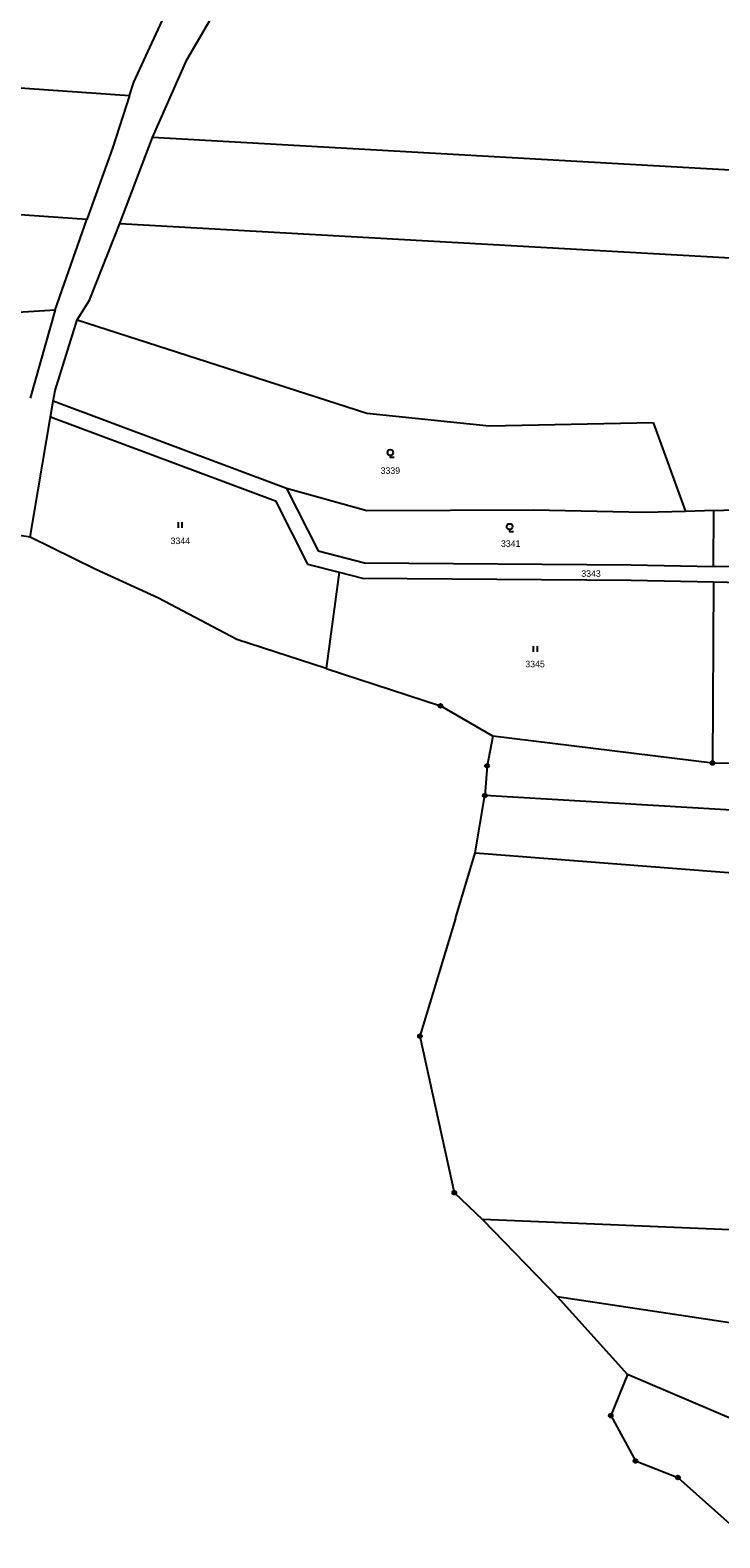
# Model space of a CAD drawing. Extents: x -618848 to -615803, y -1044450 to -1042254.
# Drawn here: x -617986.6 to -617807.4, y -1044320.6 to -1043928.7 of the extents above; entities that cross this region are included whole.
import ezdxf

# ---------------------------------------------------------------- set-up
doc = ezdxf.new("R2010")
doc.units = 0
doc.header["$LTSCALE"] = 0.68
for name, color, linetype, lineweight in [('1', 7, 'Continuous', 25), ('3', 7, 'Continuous', 25), ('8', 7, 'Continuous', 25)]:
    doc.layers.add(name, color=color, linetype=linetype, lineweight=lineweight)
doc.layers.add('2', color=7, linetype='Continuous')

msp = doc.modelspace()

# ---------------------------------------------------------------- linework, layer by layer
at = {"layer": '1'}
for p, q in [((-617959.62, -1043942.21), (-617950.21, -1043921.71)), ((-617945.87, -1043936.37), (-617936.21, -1043919.8)), ((-618090.57, -1043936.58), (-617960.75, -1043945.7)), ((-617954.79, -1043956.59), (-617945.87, -1043936.37)), ((-617960.75, -1043945.7), (-617959.62, -1043942.21)), ((-617960.75, -1043945.7), (-617965.15, -1043959.31)), ((-617963.26, -1043978.9), (-617954.79, -1043956.59)), ((-617810.87, -1043964.7), (-617954.79, -1043956.59)), ((-617965.15, -1043959.31), (-617971.8, -1043977.92)), ((-617666.94, -1043972.8), (-617810.87, -1043964.7)), ((-617971.8, -1043977.92), (-618093.61, -1043969.36)), ((-617980.1, -1044001.34), (-617971.8, -1043977.92)), ((-617971.13, -1043998.89), (-617963.26, -1043978.9)), ((-617963.26, -1043978.9), (-617816.94, -1043987.14)), ((-617816.94, -1043987.14), (-617670.61, -1043995.37)), ((-617974.35, -1044003.94), (-617971.13, -1043998.89)), ((-618083.54, -1044008.12), (-617980.1, -1044001.34)), ((-617980.1, -1044001.34), (-617986.59, -1044024.38)), ((-617980.1, -1044022.31), (-617974.35, -1044003.94)), ((-617974.35, -1044003.94), (-617899.12, -1044028.25)), ((-617980.58, -1044025.14), (-617980.1, -1044022.31)), ((-617981.26, -1044029.16), (-617980.58, -1044025.14)), ((-617919.95, -1044047.83), (-617980.58, -1044025.14)), ((-617986.53, -1044060.45), (-617981.26, -1044029.16)), ((-617981.26, -1044029.16), (-617922.82, -1044051.03)), ((-617899.12, -1044028.25), (-617867.32, -1044031.57)), ((-617867.32, -1044031.57), (-617824.69, -1044030.71)), ((-617824.69, -1044030.71), (-617816.28, -1044053.77)), ((-617922.82, -1044051.03), (-617914.5, -1044067.46)), ((-617919.95, -1044047.83), (-617911.75, -1044064.04)), ((-617899.09, -1044053.6), (-617919.95, -1044047.83)), ((-617855.68, -1044053.44), (-617899.09, -1044053.6)), ((-617826.98, -1044054.09), (-617855.68, -1044053.44)), ((-617816.28, -1044053.77), (-617826.98, -1044054.09)), ((-617808.93, -1044053.54), (-617816.28, -1044053.77)), ((-617809.02, -1044068.1), (-617808.93, -1044053.54)), ((-617808.93, -1044053.54), (-617759.25, -1044052.05)), ((-617986.53, -1044060.45), (-617991.04, -1044059.78)), ((-617969.64, -1044068.77), (-617986.53, -1044060.45)), ((-617911.75, -1044064.04), (-617899.66, -1044067.16)), ((-617953.23, -1044076.38), (-617969.64, -1044068.77)), ((-617914.5, -1044067.46), (-617906.24, -1044069.6)), ((-617906.24, -1044069.6), (-617909.69, -1044094.66)), ((-617906.24, -1044069.6), (-617900.19, -1044071.16)), ((-617899.66, -1044067.16), (-617830.39, -1044067.65)), ((-617830.39, -1044067.65), (-617809.02, -1044068.1)), ((-617788.2, -1044068.54), (-617809.02, -1044068.1)), ((-617900.19, -1044071.16), (-617830.44, -1044071.65)), ((-617830.44, -1044071.65), (-617809.04, -1044072.1)), ((-617809.04, -1044072.1), (-617809.32, -1044119.2)), ((-617809.04, -1044072.1), (-617787.18, -1044072.56)), ((-617932.9, -1044087.11), (-617953.23, -1044076.38)), ((-617909.69, -1044094.66), (-617932.9, -1044087.11)), ((-617909.69, -1044094.66), (-617879.95, -1044104.33)), ((-617866.32, -1044112.2), (-617879.95, -1044104.33)), ((-617866.32, -1044112.2), (-617867.85, -1044119.94)), ((-617867.85, -1044119.94), (-617868.44, -1044127.67)), ((-617870.92, -1044142.59), (-617868.44, -1044127.67)), ((-617790.18, -1044132.28), (-617868.44, -1044127.67)), ((-617876.05, -1044159.64), (-617870.92, -1044142.59)), ((-617870.92, -1044142.59), (-617790.88, -1044148.81)), ((-617876.05, -1044159.64), (-617885.29, -1044190.21)), ((-617885.29, -1044190.21), (-617876.38, -1044230.9)), ((-617876.38, -1044230.9), (-617869.01, -1044237.88)), ((-617869.01, -1044237.88), (-617849.67, -1044257.87)), ((-617784.3, -1044241.37), (-617869.01, -1044237.88)), ((-617849.67, -1044257.87), (-617831.39, -1044278.13)), ((-617849.67, -1044257.87), (-617787.93, -1044267.22)), ((-617831.39, -1044278.13), (-617835.71, -1044288.86)), ((-617782.08, -1044299.3), (-617831.39, -1044278.13)), ((-617835.71, -1044288.86), (-617829.3, -1044300.65)), ((-617829.3, -1044300.65), (-617818.27, -1044304.96))]:
    msp.add_line(p, q, dxfattribs=at)
for points in [[(-617714.6, -1044119.56), (-617809.32, -1044119.2), (-617866.32, -1044112.2)], [(-617818.27, -1044304.96), (-617803.97, -1044317.65), (-617795.59, -1044320.64)]]:
    msp.add_lwpolyline(points, dxfattribs=at)
at = {"layer": '3'}
for p, q in [((-617948.061, -1044058.05), (-617948.061, -1044056.55)), ((-617947.06, -1044058.05), (-617947.06, -1044056.55)), ((-617855.781, -1044090.29), (-617855.781, -1044088.79)), ((-617854.78, -1044090.29), (-617854.78, -1044088.79))]:
    msp.add_line(p, q, dxfattribs=at)
for points in [[(-617892.99, -1044039.212), (-617892.99, -1044039.71), (-617891.989, -1044039.71)], [(-617861.99, -1044058.482), (-617861.99, -1044058.98), (-617860.989, -1044058.98)]]:
    msp.add_lwpolyline(points, dxfattribs=at)
for centre in [(-617892.9893, -1044038.4609), (-617861.9893, -1044057.7309)]:
    msp.add_circle(centre, 0.75, dxfattribs=at)
at = {"layer": '8'}
for centre, radius in [((-617879.95, -1044104.3299), 0.5), ((-617879.95, -1044104.3299), 0.0303), ((-617867.85, -1044119.9399), 0.5), ((-617867.85, -1044119.9399), 0.0303), ((-617809.32, -1044119.1999), 0.5), ((-617809.32, -1044119.1999), 0.0303), ((-617868.44, -1044127.6699), 0.5), ((-617868.44, -1044127.6699), 0.0303), ((-617885.29, -1044190.2099), 0.5), ((-617885.29, -1044190.2099), 0.0303), ((-617876.38, -1044230.8999), 0.5), ((-617876.38, -1044230.8999), 0.0303), ((-617835.71, -1044288.8599), 0.5), ((-617835.71, -1044288.8599), 0.0303), ((-617829.3, -1044300.6499), 0.5), ((-617829.3, -1044300.6499), 0.0303), ((-617818.27, -1044304.9599), 0.5), ((-617818.27, -1044304.9599), 0.0303)]:
    msp.add_circle(centre, radius, dxfattribs=at)

# ---------------------------------------------------------------- texts
at = {"layer": '2'}
for s, p in [('3339', (-617895.51, -1044044.035)), ('3344', (-617950.07, -1044062.285)), ('3341', (-617864.25, -1044063.005)), ('3343', (-617843.37, -1044070.795)), ('3345', (-617857.92, -1044094.315))]:
    msp.add_text(s, height=1.7, dxfattribs=at).set_placement(p)

doc.saveas('drawing.dxf')
